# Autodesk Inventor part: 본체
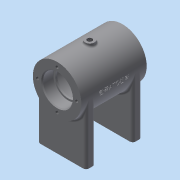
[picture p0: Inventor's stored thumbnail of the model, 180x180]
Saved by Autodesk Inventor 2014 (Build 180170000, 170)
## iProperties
Created: 2020-07
Part Number: 본체
Material: Generic
Document SubType Name: Modeling
Designer: kh
Density: 1 g/cm^3
Appearance: Default
Mass: 113.054 g
Surface Area: 357.567 cm^2
Volume: 113.054 cm^3
Author: kh
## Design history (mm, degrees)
sketch "Sketch1"
  geometry: C1 r 26 at (0, 0); 1 further point
  constraints: 1 centre point, 1 coincident
  dimensions: "d0" = 52 diameter of C1
extrude "Extrusion1" new body sketch "Sketch1" distance "d1" = 70; taper "d2" = 0 deg
workplane "Work Plane1"
sketch "Sketch2"
  geometry: L1 (-26, 0)-(26, 0); L2 (26, 0)-(26, -64); L3 (26, -64)-(-26, -64); L4 (-26, -64)-(-26, 0); 2 further points
  constraints: 8 end point, 2 coincident, 2 parallel, 1 horizontal, 1 midpoint, 1 perpendicular
  dimensions: "d4" = 64 distance from line of L3 point (0, 0); "d5" = 52 distance of L2.end L3.end
extrude "Extrusion2" join sketch "Sketch2" distance "d6" = 10; taper "d7" = 0 deg
workplane "Work Plane2"
mirror "Mirror1"
sketch "Sketch3"
  geometry: L1 (-26, 0)-(26, 0) reference; L2 (0, 70)-(0, 0); L3 (16, 70)-(16, 58); L4 (16, 58)-(14, 58); L5 (14, 58)-(14, 56); L6 (14, 56)-(21, 56); L7 (21, 56)-(21, 14); L8 (21, 14)-(14, 14); L9 (14, 14)-(14, 12); L10 (14, 12)-(16, 12); L11 (16, 12)-(16, 0); L12 (0, 0)-(16, 0); L13 (26, 70)-(-26, 70) reference; L14 (16, 70)-(0, 70); 2 further points
  constraints: 24 end point, 6 parallel, 3 perpendicular, 2 collinear, 2 midpoint, 1 horizontal alignment, 1 point on line
  dimensions: "d9" = 32 diameter of L3 L2; "d10" = 32 diameter of L11 L2; "d11" = 28 diameter of L5 L2; "d12" = 28 diameter of L9 L2; "d13" = 42 diameter of L7 L2; "d14" = 35 distance from line of point (21, 35) L13; "d15" = 12 distance of L3.start L3.end; "d16" = 12 distance of L10.end L11.end; "d17" = 2 distance of L4.end L5.end
revolve "Revolution1" sketch "Sketch3" stored, may be unused: angle "d18" = 90 deg
sketch "Sketch4"
  geometry: L1 (0, 0)-(0, -26); L2 (0, 0)-(-8.893, -24.432); L3 (0, 0)-(-24.195, 8.806); L4 (-9.919, -27.251)-(-33.512, -18.664); L5 (-9.919, -27.251)-(-4.28, -29.303); L6 (-4.28, -29.303)-(-3.014, -25.825); L7 (-8.893, -24.432)-(-9.919, -27.251); A1 r 26 centre (0, 0) between (-26, 0) and (26, 0) reference; A2 r 6 centre (-9.919, -27.251) between (-4.28, -29.303) and (-13.336, -22.319); A3 r 26 centre (0, 0) between (0, -26) and (-13.336, -22.319); A4 r 26 centre (0, 0) between (-8.893, -24.432) and (-3.014, -25.825); 4 further points
  constraints: 14 end point, 9 point on circle, 3 centre point, 3 coincident, 2 parallel, 2 perpendicular, 1 collinear, 1 point on line, 1 tangent
  dimensions: "d19" = 20 deg angle of L2 L1; "d21" = 29 distance between parallel lines of L4 L3; "d23" = 12 diameter of A2
revolve "Revolution2" sketch "Sketch4" stored, may be unused: angle "d24" = 90 deg
workplane "Work Plane3"
sketch "Sketch5"
  geometry: L1 (26, 70)-(-26, 70) reference; C1 r 5 at (0, 35); 1 further point
  constraints: 1 centre point
  dimensions: "d26" = 10 diameter of C1; "d27" = 35 distance from line of C1.centre L1
extrude "Extrusion3" join sketch "Sketch5" stored distance "d28" = 10; taper "d29" = 0 deg
hole "Hole1" diameter "d32" = 5.188; stored, may be unused: countersink angle "d36" = 90 deg, drill point angle "d38" = 118 deg; dims "d33" = 6, "d34" = 4, "d35" = 2, "d37" = 19.75, "d80" = 10, "d81" = 10
hole "Hole2" diameter "d41" = 5.188; stored, may be unused: countersink angle "d45" = 90 deg, drill point angle "d47" = 118 deg; dims "d42" = 6, "d43" = 4, "d44" = 2, "d46" = 19.75, "d82" = 10, "d83" = 10
sketch "Sketch6"
  geometry: C1 r 26 at (0, 0) reference; A1 r 21 centre (0, 0) between (0, 21) and (-21, 0); 2 further points
  constraints: 4 point on circle, 1 centre point, 1 coincident
  dimensions: "d48" = 42 diameter of A1
hole "Hole3" sketch "Sketch6" at (0, 21), (-21, 0), (21, 0), (0, -21) diameter "d49" = 3.242; stored, may be unused: countersink angle "d53" = 90 deg, drill point angle "d55" = 118 deg; dims "d50" = 8, "d51" = 4, "d52" = 2, "d54" = 10
mirror "Mirror2"
sketch "Sketch7"
  geometry: L1 (52, 0)-(0, 0) reference; L2 (52, 0)-(52, -10) reference; L3 (26, 0)-(26, -46.152); 3 further points
  constraints: 2 end point, 1 midpoint, 1 parallel
  dimensions: "d56" = 5 distance from line of point (46, -5) L1; "d57" = 5 distance from line of point (6, -5) L1; "d58" = 20 distance from line of point (46, -5) L3; "d59" = 20 distance from line of L3 point (6, -5)
hole "Hole4" sketch "Sketch7" at (46, -5), (6, -5) diameter "d60" = 4.134; stored, may be unused: countersink angle "d64" = 90 deg, drill point angle "d66" = 118 deg; dims "d61" = 8.608, "d62" = 4, "d63" = 2, "d65" = 10
mirror "Mirror3"
workplane "Work Plane4"
sketch "Sketch8"
  geometry: L1 (26, 70)-(-26, 70) reference; L2 (26, 0)-(26, 70) reference; 2 further points
  constraints: 1 other
  dimensions: "d68" = 35 distance from line of point (0, 35) L1; "d69" = 26 distance from line of L2 point (0, 35)
emboss "Emboss1" sketch "Sketch8" dims "d9" = 32, "d10" = 32, "d11" = 28, "d12" = 28, "d13" = 42, "d14" = 35, "d15" = 12, "d16" = 12, "d17" = 2, "d70" = 0.5, "d71" = 0
chamfer "Chamfer1" distance "d72" = 1; stored, may be unused: second distance "d73" = 2, angle "d74" = 45 deg
fillet "Fillet1" dims "d75" = 3
fillet "Fillet2" dims "d76" = 2
fillet "Fillet3" dims "d77" = 0.3, "d78" = 3
fillet "Fillet4" dims "d79" = 3
body "Solid1"
other parameters: "d3" = -5, "d8" = -35, "d25" = 29, "d67" = 26
